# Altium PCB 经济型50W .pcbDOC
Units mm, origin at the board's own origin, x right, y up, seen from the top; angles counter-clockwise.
Board outline 67 x 32 mm, 2 copper layers (Top Layer, Bottom Layer); 38 components, 38 nets, 95 pads, 0 vias.
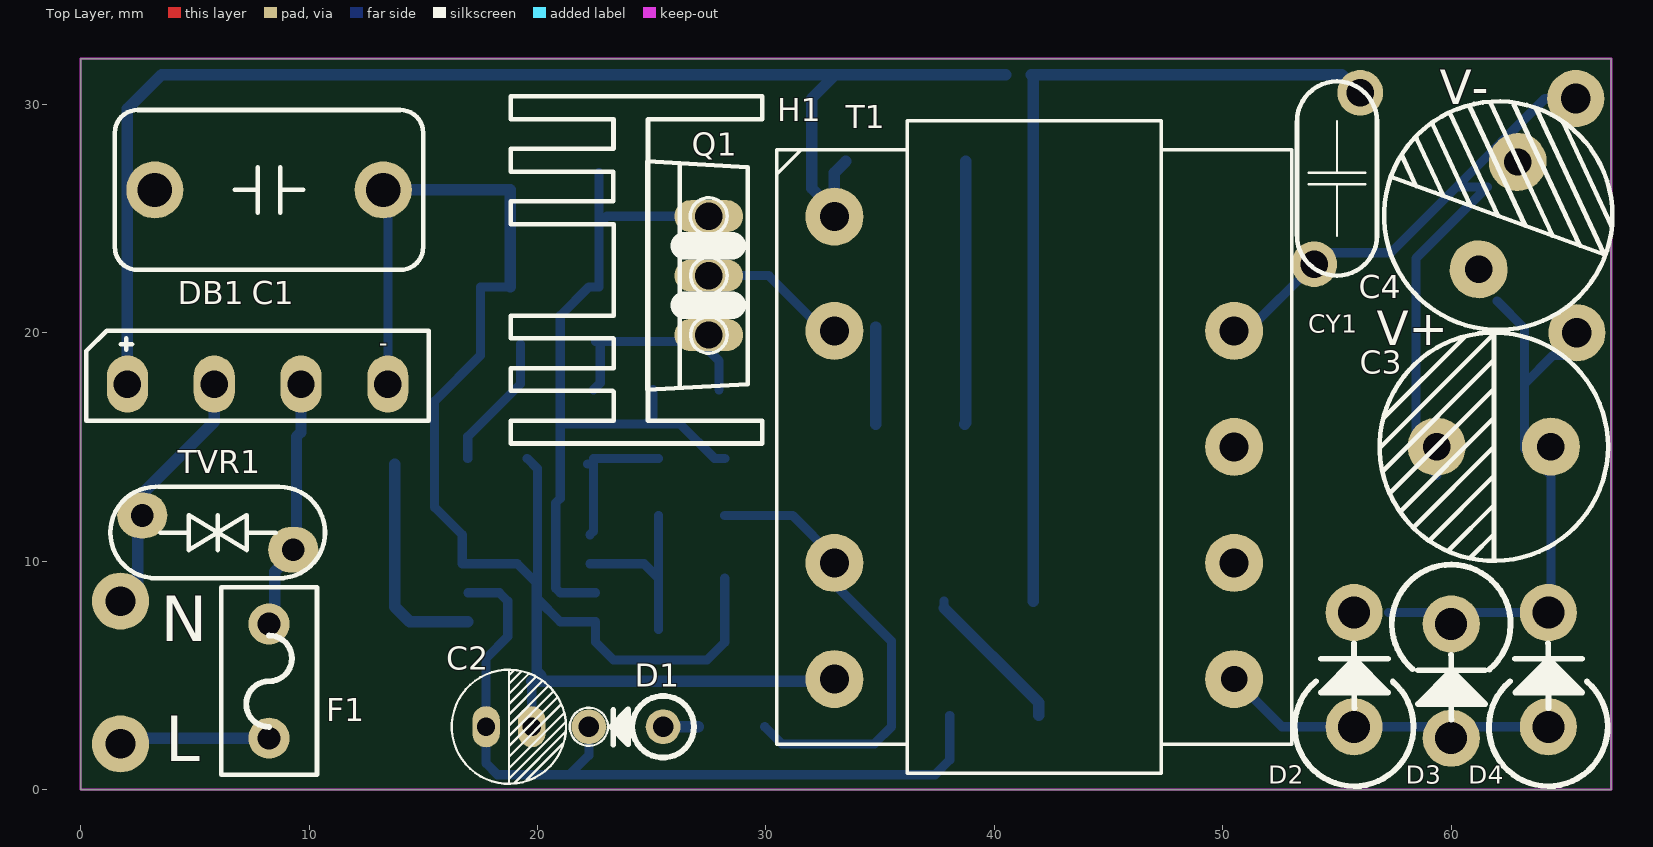
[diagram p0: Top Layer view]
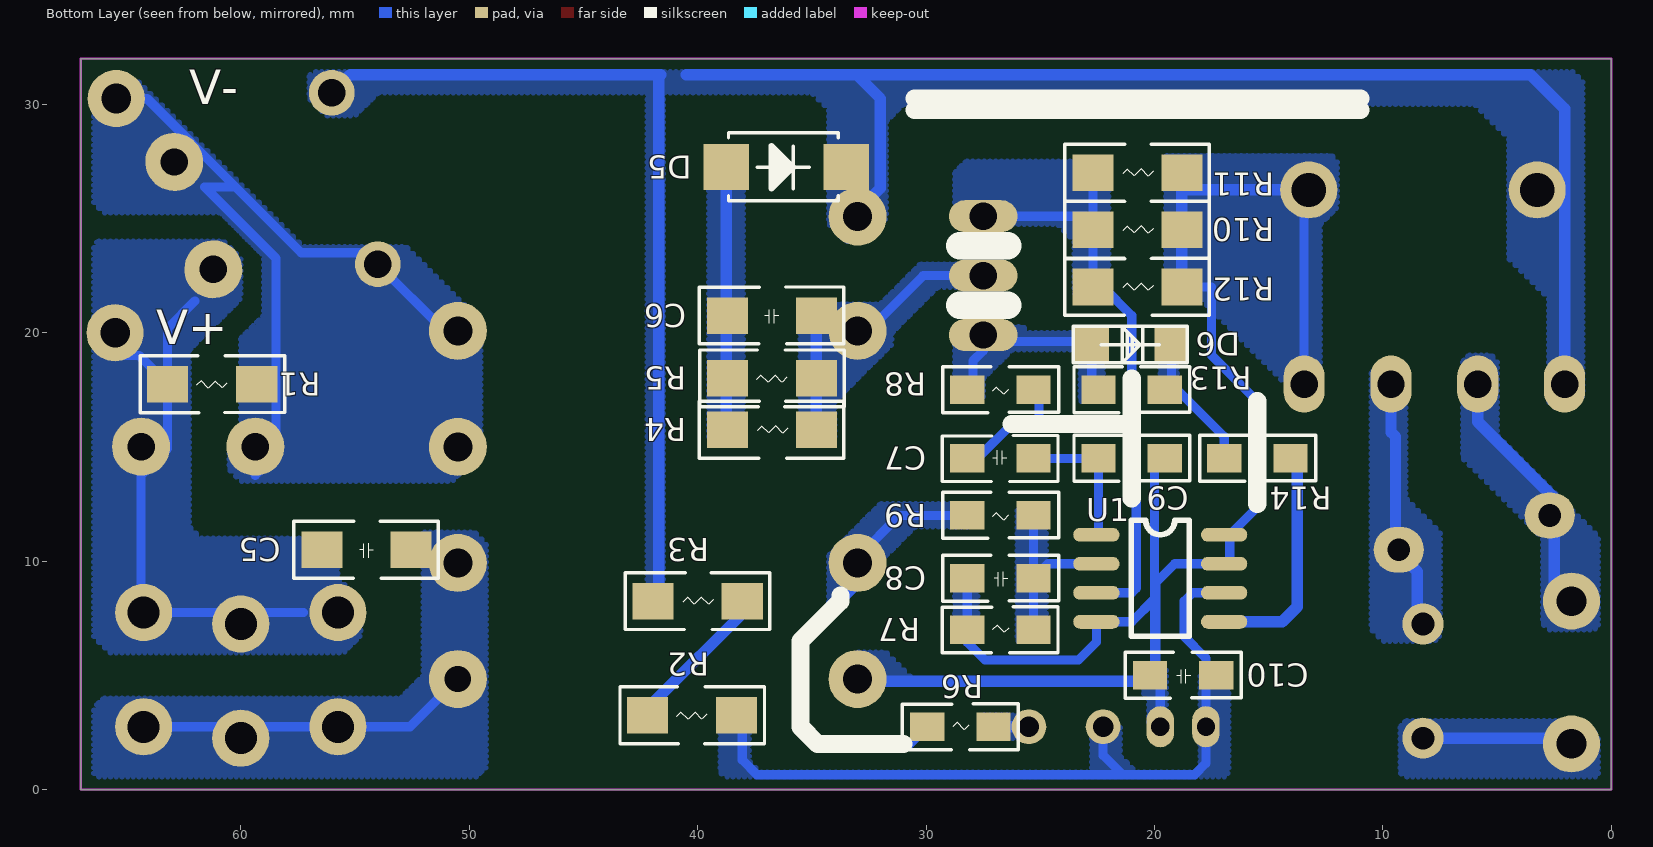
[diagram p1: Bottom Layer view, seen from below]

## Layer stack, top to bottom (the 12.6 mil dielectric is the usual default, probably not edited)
Top Solder: solder mask 0.0102, Solder Resist, Dk 3.5
Top Layer: signal copper 0.0356
Dielectric 1: dielectric 0.32, FR-4, Dk 4.8
Bottom Layer: signal copper 0.0356
Bottom Solder: solder mask 0.0102, Solder Resist, Dk 3.5

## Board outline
0,0 0,32 67,32 67,0

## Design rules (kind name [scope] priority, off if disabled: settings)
Clearance [All] p1: gap=0.4
FanoutControl Fanout_LCC [All] p1 off: bgadir=Out bgaviamode=Centered fanoutstyle=Auto fanoutdirection=Alternating viagrid=0.025 // Protel DXP Scope 1 Expression Was: IsLCC   Fanout_LCC (Default Rule)
FanoutControl Fanout_BGA [All] p2 off: bgadir=Out bgaviamode=Centered fanoutstyle=Auto fanoutdirection=Alternating viagrid=0.025 // Protel DXP Scope 1 Expression Was: IsBGA   Fanout_BGA (Default Rule)
FanoutControl Fanout_SOIC [All] p3 off: bgadir=Out bgaviamode=Centered fanoutstyle=Auto fanoutdirection=Alternating viagrid=0.025 // Protel DXP Scope 1 Expression Was: IsSOIC   Fanout_SOIC (Default Rule)
FanoutControl Fanout_Default [All] p4: bgadir=Out bgaviamode=Centered fanoutstyle=Auto fanoutdirection=Alternating viagrid=0.025 // Fanout_Default (Default Rule)
FanoutControl Fanout_Small [All] p5 off: bgadir=Out bgaviamode=Centered fanoutstyle=Auto fanoutdirection=Alternating viagrid=0.025 // Protel DXP Scope 1 Expression Was: (CompPinCount < 5)   Fanout_Small (Default Rule)
PlaneConnect [All] p1: planeconnectstyle=Direct reliefexpansion=0.508 reliefentries=4 reliefconductorwidth=0.254 reliefairgap=0.254
PolygonConnect [All] p1: connectstyle=Direct reliefconductorwidth=0.254 reliefentries=4 polygonreliefangle="90 Angle" airgapwidth=0.254
RoutingLayers [All] p1: top layer_v5=FALSE bottom layer_v5=TRUE
RoutingVias [All] p1: holewidth=0.711 width=1.27 viastyle="Through Hole" minholewidth=0.711 minwidth=1.27 maxholewidth=0.711 maxwidth=1.27
SilkToSolderMaskClearance [All] p1 off: minsilkscreentomaskgap=0.254 clearancetoexposedcopper=TRUE // Protel DXP Scope 1 Expression Was: IsPad
SolderMaskExpansion [All] p1: expansion=0.102
Width [All] p1: maxlimit=1 minlimit=0.2 preferedwidth=0.254
21 further rules are at their usual default settings.

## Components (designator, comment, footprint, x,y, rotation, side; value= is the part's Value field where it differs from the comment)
C1 "474 400V" "CBB电容 脚距10 长13mm 宽5mm" 8.25,26.25 r0 top
C2 "22uF/50V" "电解电容 脚距2mm 外径5mm" 18.75,2.75 r180 top
C3 "470uF 50V" "电解电容 脚距5mm 外径10mm" 62,15 r180 top
C4 "470uF 50V" "电解电容 脚距5mm 外径10mm" 62,25 r70 top
C5 "102/1KV" "电容 1206 背贴" 54.5,10.5 r180 bottom
C6 "103/1KV" "电容 1206 背贴" 36.75,20.75 r180 bottom
C7 "104 50V" "电容 0805 背贴"#1 26.75,14.5 r180 bottom
C8 "22pF 25V" "电容 0805 背贴"#1 26.75,9.25 r0 bottom
C9 "474 50V" "电容 0805 背贴"#1 21,14.5 r0 bottom
C10 "104/50V" "电容 0805 背贴"#2 18.75,5 r180 bottom
CY1 "102/250VAC" "Y2 电容 脚距7.5mm" 55,26.75 r90 top
D1 "1N4007" "二极管 DO41 脚距3.0mm" 25.5,2.75 r180 top
D2 "SF56" "二极管 DO201 脚距5.0MM" 55.75,5.25 r90 top
D3 "SF56" "二极管 DO201 脚距5.0mm_1" 60,4.75 r90 top
D4 "SF56" "二极管 DO201 脚距5.0MM" 64.25,5.25 r90 top
D5 "RS1M" "二极管 SMA" 36.25,27.25 r180 bottom
D6 "1N4148" "二极管 LL34" 21,19.5 r180 bottom
DB1 "KBP210" "桥堆 KBP" 7.75,17.75 r0 top
F1 "3.15A 250VAC" "保险丝 脚距5mm 长8mm 宽4mm" 8.25,4.75 r270 top
H1 "散热器" "散热片 长15mm 宽11mm 铝型材" 23.5,22.75 r0 top locked
Q1 "7N65" "功率开关管 TO220F-2" 27.5,22.5 r90 top
R1 "22K 5%" "电阻 1206 背贴"#1 61.25,17.75 r0 bottom
R2 "300K 5%" "电阻 1206 背贴"#2 40.25,3.25 r180 bottom
R3 "300K 5%" "电阻 1206 背贴"#2 40,8.25 r0 bottom
R4 "200K 5%" "电阻 1206 背贴"#1 36.75,15.75 r180 bottom
R5 "200K 5%" "电阻 1206 背贴"#1 36.75,18 r0 bottom
R6 "47R 5%" "电阻 0805 背贴"#1 28.5,2.75 r180 bottom
R7 "10K 1%" "电阻 0805 背贴"#2 26.75,7 r0 bottom
R8 "10K 5%" "电阻 0805 背贴"#2 26.75,17.5 r180 bottom
R9 "51K 1%" "电阻 0805 背贴"#2 26.75,12 r180 bottom
R10 "0.75R 1%" "电阻 1206 背贴"#2 20.75,27 r0 bottom
R11 "0.75R 1%" "电阻 1206 背贴"#2 20.75,24.5 r0 bottom
R12 "0.75R 1%" "电阻 1206 背贴"#2 20.75,22 r0 bottom
R13 "47R 5%" "电阻 0805 背贴"#1 21,17.5 r0 bottom
R14 "22R 5%" "电阻 0805 背贴"#2 15.5,14.5 r180 bottom
T1 "EFD25" 变压器ee28(5+5) 41.75,15 r0 top
TVR1 "7D511" "压敏电阻 直径7mm" 6,11.25 r90 top
U1 "LZC811C" "集成电路 SOP8 LZC811B" 19.75,9.25 r180 bottom

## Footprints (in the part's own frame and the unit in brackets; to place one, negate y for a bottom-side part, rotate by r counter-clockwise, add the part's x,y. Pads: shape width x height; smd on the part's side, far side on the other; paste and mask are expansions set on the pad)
"CBB电容 脚距10 长13mm 宽5mm" [mm] "插件"
  round 2.5 hole 1.5: 1(-5,0) 2(5,0)
  silkscreen extent -6.75,-3.5 6.75,3.5
"Y2 电容 脚距7.5mm" [mm] "插件"
  round 2 hole 1.2: 1(-3.75,1) 2(3.75,-1.016)
  silkscreen extent -4.25,-1.75 4.25,1.75
"二极管 DO41 脚距3.0mm" [mil] "插件"
  round 60 hole 35.43: 1(0,0) 2(127.95,0)
  silkscreen extent -53,-53 161,53
"二极管 DO201 脚距5.0MM" [mm] "插件"
  round 2.5 hole 1.4: 1(-2.5,0) 2(2.5,0)
  silkscreen extent -5.1,-2.6 1.15,2.6
"二极管 DO201 脚距5.0mm_1" [mm] "插件"
  round 2.5 hole 1.4: 1(-2.5,0) 2(2.5,0)
  silkscreen extent -1.68,-2.6 5.1,2.6
"二极管 LL34" [mm] "贴片"
  rect 1.5x1.5 smd: 1(-1.75,0) 2(1.75,0)
  silkscreen extent -2.56,-0.82 2.44,0.78
"二极管 SMA" [mm] "贴片"
  rect 2x2 smd: 1(-2.5,0) 2(2.75,0)
  silkscreen extent -2.4,-1.48 2.4,1.49
"保险丝 脚距5mm 长8mm 宽4mm" [mm] "贴片"
  round 1.8 hole 1: 1(-2.5,0) 2(2.5,0)
  silkscreen extent -4.1,-2.1 4.1,2.1
"功率开关管 TO220F-2" [mm] "插件"
  oval 1.4x3 hole 1.2: D(0,0) G(-2.6,0) S(2.6,0)
  silkscreen extent -5,-1.7 5,2.7
"压敏电阻 直径7mm" [mm] "插件"
  oval 2x2.2 hole 1: 1(-0.75,-3.31) 2(0.75,3.3)
  silkscreen extent -2,-4.7 2,4.7
变压器ee28(5+5) [mm] "插件"
  round 0 all layers, no hole: 0(8.75,5.08) ""(-8.731,10.16)
  round 2.54 hole 1.27: 1(-8.75,10.08) 2(-8.75,5.08) 4(-8.75,-5.08) 5(-8.75,-10.16) 7(8.75,-5.08) 8(8.75,0) 9(8.75,5.08)
  round 2.54 hole 1.143: 6(8.75,-10.16)
  silkscreen extent -11.27,-14.29 11.27,14.29
"散热片 长15mm 宽11mm 铝型材" [mm] "配件"
  silkscreen extent -4.66,-7.6 6.34,7.6
"桥堆 KBP" [mm] "插件"
  oval 1.8x2.5 hole 1.2: 1(-5.7,0) 2(-1.9,0) 3(1.9,0) 4(5.7,0)
  silkscreen extent -7.5,-1.6 7.5,2.34
"电容 0805 背贴"#1 [mm] "贴片"
  rect 1.5x1.25 smd: 1(1.45,0) 2(-1.45,0)
  silkscreen extent -2.55,-1.01 2.52,1
"电容 0805 背贴"#2 [mm] "贴片"
  rect 1.5x1.25 smd: 1(-1.45,0) 2(1.45,0)
  silkscreen extent -2.52,-1 2.55,1.01
"电容 1206 背贴" [mm] "贴片"
  rect 1.8x1.6 smd: 1(-1.95,0) 2(1.95,0)
  silkscreen extent -3.17,-1.24 3.15,1.25
"电解电容 脚距2mm 外径5mm" [mm] "插件"
  oval 1.2x1.8 hole 0.8: 1(1,0) 2(-1,0)
  silkscreen extent -2.5,-2.5 2.5,2.5
"电解电容 脚距5mm 外径10mm" [mm] "插件"
  round 2.54 hole 1.2: 1(-2.364,-0.01) 2(2.636,-0.01)
  silkscreen extent -4.86,-5.01 5.13,4.99
"电阻 0805 背贴"#1 [mm] "贴片"
  rect 1.5x1.25 smd: 1(1.45,0) 2(-1.45,0)
  silkscreen extent -2.55,-1.01 2.52,1
"电阻 0805 背贴"#2 [mm] "贴片"
  rect 1.5x1.25 smd: 1(-1.45,0) 2(1.45,0)
  silkscreen extent -2.52,-1 2.55,1.01
"电阻 1206 背贴"#1 [mm] "贴片"
  rect 1.8x1.6 smd: 1(-1.95,0) 2(1.95,0)
  silkscreen extent -3.17,-1.24 3.15,1.25
"电阻 1206 背贴"#2 [mm] "贴片"
  rect 1.8x1.6 smd: 1(1.95,0) 2(-1.95,0)
  silkscreen extent -3.15,-1.25 3.17,1.24
"集成电路 SOP8 LZC811B" [mil] "贴片"
  oval 80x24 smd: CMP(-110,75) CS(-110,-25) DRV(110,-75) FB(-110,25) GND(-110,-75) NC(110,25) NC(110,75) VDD(110,-25)
  silkscreen extent -50,-100 50,100

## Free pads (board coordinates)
  round 2.5 hole 1.3: 0(1.75,8.25) 1(1.75,2) 1(65.453,30.25) 1(65.5,20)

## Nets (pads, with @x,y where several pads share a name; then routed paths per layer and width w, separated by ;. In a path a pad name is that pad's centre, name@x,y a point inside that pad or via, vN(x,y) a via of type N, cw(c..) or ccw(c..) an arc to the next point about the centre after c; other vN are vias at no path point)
CMP: C7.1 C9.1 U1.CMP | length 6.3
  Bottom Layer w0.4: C9.1@22.2,14.25 22.45,14.25 22.45,11.311 U1.CMP@22.294,11.155 ; C9.1 C7.1
CS: C7.2 Q1.S R8.2 R10.1 R11.1 R12.1 U1.CS | length 35.5
  Bottom Layer w0.4: U1.CS 21,8.615 20.8,8.815 20.8,12.55 21,12.75 21,15.665 21,16 ; R10.1 R11.1@22.7,24.75 ; R8.2@25.05,17.5 25.05,16.3 24.75,16 ; Q1.S 23.05,25.1 R11.1@22.7,24.75 ; C7.2 27.75,14.5 26.25,16 24.75,16 ; 21,16 24.75,16 ; 21,16 21,20.75 22.25,22 R12.1 R11.1 R11.1@22.7,24.75
DRV: R14.2 U1.DRV | length 9.7
  Bottom Layer w0.5: R14.2@13.75,14.25 13.75,8 14.405,7.345 U1.DRV
E: 
E2: 
E3: 
FB: C8.2 R7.1 R9.2 U1.FB | length 8.3
  Bottom Layer w0.4: U1.FB@22.294,9.885 24.665,9.885 C8.2 ; R7.1 R9.2
G: D6.2 R13.2 R14.1 | length 6
  Bottom Layer w0.4: R14.1 16.95,15.45 19.25,17.75 D6.2
G1: 
g2: D6.1 Q1.G R8.1 R13.1 | length 9.2
  Bottom Layer w0.4: R13.1 22.75,17.8 D6.1 ; D6.1@22.547,19.61 27.297,19.61 27.5,19.21 27.95,18.76 R8.1@27.95,17.5
GND: C3.2 C4.2 CY1.1 pad.1@65.453,30.25 R1.1 T1.8 T1.9 | length 35.2
  Bottom Layer w0.4: T1.9 51.08,20.08 CY1.1 54.5,23.5 57.354,23.5 60.24,26.386 ; C3.2@59.364,13.76 58.453,14.672 58.453,23.25 61.588,26.386 60.24,26.386 ; pad.1@65.5,29.5 64.75,30.25 64.104,30.25 60.24,26.386
GND1: 
GND2: 
GNDE: C1.2 C2.2 C8.1 C9.2 C10.1 DB1.4 R7.2 R10.2 R11.2 R12.2 T1.5 U1.GND U1.NC | length 79.5
  Bottom Layer w0.4: C1.2@12.75,26.25 13.45,25.55 DB1.4 DB1.4@13.45,17.465 ; R12.2 17.5,22 17.5,19 15.5,17 15.5,12.361 16.706,11.155 16.706,9.885 19.115,9.885 19.949,9.051 19.949,5 19.75,4.801 19.75,4.75 C2.2 ; C9.2 20,14.05 20,8.342 ; C10.1 20,5.2 20,8.342 ; 20.5,7.842 20,8.342 ; C8.1 28.2,6.45 27.425,5.675 23.325,5.675 22.544,6.456 U1.GND 20.997,7.345 20,8.342
  Bottom Layer w0.5: C1.2@12.75,26.25 18.8,26.25 R11.2 R12.2 ; C10.1@19.75,4.75 T1.5@31.75,4.75
HV1: C6.1 D5.1 R4.1 R5.2 | length 11.5
  Bottom Layer w0.5: R4.1@38.7,16 38.75,16.05 D5.1@38.75,27.5
L: F1.2 pad.1@1.75,2 | length 6
  Bottom Layer w0.5: pad.1@1.75,2.25 F1.2@7.75,2.25
L0: DB1.3 F1.1 TVR1.1 | length 11.3
  Bottom Layer w0.5: F1.1@7.75,7.25 8.5,8 8.5,9.547 9.453,10.5 9.453,15.453 9.65,15.65 DB1.3
L1: 
L2: 
LED+: 
LED-: 
LN: 
N: 
N0: DB1.2 pad.0 TVR1.2 | length 11.9
  Bottom Layer w0.5: pad.0 2.5,9 2.5,12.25 2,12.25 5.85,16.1 DB1.2
N1: 
N3: 
ST: R2.2 R3.2 | length 6.7
  Bottom Layer w0.4: R3.2@37.8,7.95 R3.2@37.8,8.25
  Bottom Layer w0.5: R3.2@37.8,7.95 41.95,3.8 R2.2@41.95,3.25
TA: R6.2 R9.1 T1.4 | length 20.2
  Bottom Layer w0.4: R9.1 31.17,12 33,10.17 33,9 35.5,6.5 35.5,2.75 34.75,2 30.7,2 R6.2
TA1: D1.1 R6.1 | length 1.8
  Bottom Layer w0.5: D1.1@25.25,2.75 R6.1
TS: C5.2 D2.1 D3.1 D4.1 T1.6 T1.7 | length 14.4
  Bottom Layer w0.4: T1.6 52.59,2.75 57.25,2.75 D4.1@64,2.75
TS1: 
VBUS: C1.1 CY1.2 D5.2 DB1.1 R3.1 T1.1 | length 98.1
  Bottom Layer w0.5: DB1.1 2.05,29.8 3.55,31.3 33.05,31.3 ; D5.2@33.5,27.5 33,27 33,25.33 32,26.33 32,30.25 33.05,31.3 ; 40.5,31.3 33.05,31.3 ; R3.1@41.7,8.25 41.7,31.215 41.615,31.3 55.216,31.3 CY1.2
VBUS1: 
VBUS2: 
VBUS3: 
VDD: C2.1 C10.2 D1.2 R2.1 U1.VDD | length 34.8
  Bottom Layer w0.4: U1.VDD 18.335,8.615 18.7,8.25 18.7,6.7 17.75,5.75 C2.1 17.75,1.15 18.25,0.65 37.4,0.65 38.05,1.3 R2.1@38.05,3.25 ; 21.4,0.65 22.25,1.5 22.25,2.25 D1.2@22.75,2.75
VDS: C6.2 Q1.D R4.2 R5.1 T1.2 | length 10.6
  Bottom Layer w0.4: Q1.D 30.125,22.5 32.295,20.33 T1.2@33,20.33
  Bottom Layer w0.5: R4.2@34.8,16 34.8,17.375 C6.2@34.8,20.25
VOUT: C3.1 C4.1 C5.1 D2.2 D3.2 D4.2 pad.1@65.5,20 R1.2 | length 24.3
  Bottom Layer w0.4: 57.25,7.75 64,7.75 64.364,8.114 64.364,13.76 63.2,14.925 R1.2 ; 62.01,21.386 63.2,20.196 R1.2 ; pad.1@65.5,19 64.45,19 R1.2
pads on no net: T1. T1.0

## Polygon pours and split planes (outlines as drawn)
no net on Keep-Out Layer (hatched 90Degree grid 0.2 track 0.2): 25.335,8.035
no net on Keep-Out Layer (hatched 90Degree grid 0.2 track 0.2): 99.31,2.685
no net on Keep-Out Layer (hatched 90Degree grid 0.2 track 0.203): 5.885,-7.515
L0 on Bottom Layer "Bottom Layer-No Net" (hatched 90Degree grid 0.25 track 0.25, remove dead copper, pour order 35): 10.25,18.5 10.5,18.25 10.5,7 10,6.5 7.75,6.5 7.5,6.75 7.5,11.25 9,12.75 9,18.25 9.25,18.5
N0 on Bottom Layer "Bottom Layer-No Net" (hatched 90Degree grid 0.25 track 0.25, remove dead copper, pour order 33): 0.5,11 5,15.5 5,18.75 5.25,19 6.25,19 6.5,18.75 6.5,14.5 3,11 3,7.25 2.75,7 0.75,7 0.5,7.25
GNDE on Bottom Layer "Bottom Layer-No Net" (hatched 90Degree grid 0.25 track 0.25, remove dead copper, pour order 28): 33,6 31.75,6 30.5,4.75 32,4.75 33,3.75 33.25,3.75 33.25,4.25 33.5,4.5 33.25,4.75 33.25,5.75
L on Bottom Layer "Bottom Layer-No Net" (hatched 90Degree grid 0.25 track 0.25, remove dead copper, pour order 37): 1.5,3 6.25,3 9,3 9.25,2.75 9.25,2.25 9.25,0.75 8.75,0.25 3.5,0.25 0.75,0.25 0.5,0.5 0.5,1.5 0.5,2.25 1.25,3
VBUS on Bottom Layer "Bottom Layer-No Net" (hatched 90Degree grid 0.25 track 0.25, remove dead copper, pour order 39): 1.25,17.25 1.25,31 2,31.75 56.5,31.75 57,31.25 57,30.25 56.25,29.5 55,29.5 54,30.5 35,30.5 34.25,29.75 34.25,24.75 33.5,24 32.75,24 31.75,25 31.75,29.25 31,30 6,30 4.5,28.5 4.5,23.25 2.75,21.5 2.75,17 2.5,16.75 1.75,16.75 1.5,17
VDS on Bottom Layer "Bottom Layer-No Net" (hatched 90Degree grid 0.25 track 0.25, remove dead copper, pour order 41): 26.75,22 29.5,22 31.5,20 31.5,19.5 34,17 34,15.25 35.5,15.25 35.5,21.25 32,21.25 30.25,23 26.75,23
g2 on Bottom Layer "Bottom Layer-No Net" (hatched 90Degree grid 0.25 track 0.25, remove dead copper, pour order 43): 28.75,17 27.5,17 27.5,18 26.25,19.25 23.5,19.25 23.25,19 23.25,17 22.25,17 22.25,20 25.5,20 25.75,20.25 28.75,20.25
HV1 on Bottom Layer "Bottom Layer-No Net" (hatched 90Degree grid 0.25 track 0.25, remove dead copper, pour order 45): 38,27.75 38,15.25 39.5,15.25 39.5,18.25 39.5,24 39.5,27.75
VBUS on Bottom Layer "Bottom Layer-No Net" (hatched 90Degree grid 0.25 track 0.25, remove dead copper, pour order 47): 42.203,8 42.203,30.96 41.5,30.96 41.5,8
GNDE on Bottom Layer "Bottom Layer-No Net" (hatched 90Degree grid 0.25 track 0.25, remove dead copper, pour order 49): 12.75,17.5 12.75,24.75 12,25.5 12,27.5 12.25,27.75 19.5,27.75 19.5,21.5 18,21.5 14,17.5 13.485,17.5 13.45,17.465
TA on Bottom Layer "Bottom Layer-No Net" (hatched 90Degree grid 0.25 track 0.25, remove dead copper, pour order 51): 28,12.5 31,12.5 32,12.5 33.75,10.75 34,10.5 34,9.25 33.75,9 32.75,9 32.75,9.25 31.75,10.25 30.5,11.5 28,11.5
GNDE on Bottom Layer "Bottom Layer-No Net" (hatched 90Degree grid 0.25 track 0.25, remove dead copper, pour order 53): 28.75,9.75 28.75,6.5 27.75,6.5 27.75,9.75
FB on Bottom Layer "Bottom Layer-No Net" (hatched 90Degree grid 0.25 track 0.25, remove dead copper, pour order 55): 25.75,12.25 26,12.25 26,6.5 24.75,6.5 24.75,12.25
CS on Bottom Layer "Bottom Layer-No Net" (hatched 90Degree grid 0.25 track 0.25, remove dead copper, pour order 57): 22,27.5 22,21.5 23.25,21.5 23.5,21.75 23.5,24 24.25,24.75 28.75,24.75 28.75,27 28.25,27.5
VDD on Bottom Layer "Bottom Layer-No Net" (hatched 90Degree grid 0.25 track 0.25, remove dead copper, pour order 59): 16.75,5 16.75,0.75 17.25,0.25 19.75,0.25 38.5,0.25 39,0.75 39,2.5 39,3 37.75,3 37.75,1.25 37.25,0.75 36.5,0.75 18.25,0.75 18,1 18,2.25 18,5
VDD on Bottom Layer "Bottom Layer-No Net" (hatched 90Degree grid 0.25 track 0.25, remove dead copper, pour order 61): 21.75,3 21.5,2.75 21.5,1.75 21.5,1.46 20.703,0.663 20.79,0.575 22.453,0.575 22.75,0.872 22.75,2.75 22.5,3
TA1 on Bottom Layer "Bottom Layer-No Net" (hatched 90Degree grid 0.25 track 0.25, remove dead copper, pour order 63): 25.25,3.25 27.5,3.25 27.5,2.25 25,2.25
TA on Bottom Layer "Bottom Layer-No Net" (hatched 90Degree grid 0.25 track 0.25, remove dead copper, pour order 65): 33.04,11.46 34.25,10.25 34.25,8.25 34.25,8 34,8 31.703,10.297
GNDE on Bottom Layer "Bottom Layer-No Net" (hatched 90Degree grid 0.25 track 0.25, remove dead copper, pour order 9): 19.5,2.75 19.5,5.25 20.5,5.25 20.5,4.25 20.25,4 20.25,3.25 20.25,2.75
TS on Bottom Layer "Bottom Layer-No Net" (hatched 90Degree grid 0.25 track 0.25, remove dead copper, pour order 70): 49.25,1 50,0.25 66.5,0.25 66.75,0.5 66.75,3.25 66,4 53,4 52,5 52,11.25 49.75,11.25 49.25,10.75
GND on Bottom Layer "Bottom Layer-No Net" (hatched 90Degree grid 0.25 track 0.25, remove dead copper, pour order 68): 49.5,20.5 52.75,23.75 57.25,23.75 64.5,31 66.25,31 66.75,30.5 66.75,26 66,25.25 60.875,25.25 59,23.375 59,20.75 60,19.75 60,15.25 60.5,14.75 60.5,14 60,13.5 50.75,13.5 49.5,14.75
VOUT on Bottom Layer "Bottom Layer-No Net" (hatched 90Degree grid 0.25 track 0.25, remove dead copper, pour order 72): 55.25,6.25 55.5,6 65.75,6 66.75,7 66.75,23.5 66.25,24 60.75,24 60,23.25 60,21.5 62.25,19.25 62.25,11.5 61.75,11 56,11 55.75,10.75 55.75,9.25 54.75,8.25 54.75,6.75
G on Bottom Layer "Bottom Layer-No Net" (hatched 90Degree grid 0.25 track 0.25, remove dead copper, pour order 74): 19.5,19.5 19.75,19.25 19.75,17.75 19,17.75 19,19.5

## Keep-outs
Keep-Out Layer:
  the board outline again, w0.1

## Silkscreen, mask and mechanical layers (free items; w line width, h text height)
Top Overlay:
  text "V-" at 59.5,30 h1.5
  text "V+" at 56.75,19.46 h1.5
  text "N" at 3.5,6.5 h2
  text "L" at 3.703,1.25 h2
Bottom Overlay:
  lines w0.8: 11,29.75 30.5,29.75 ; 11,30.25 30.5,30.25 ; 15.5,12.5 15.5,17 ; 21,12.75 21,18 ; 21,16 26.25,16 ; 31,2 34.75,2 35.5,2.75 ; 33.75,8.5 33.75,8.25 35.5,6.5 35.5,5 35.5,2.75 ; 35.5,2.75 35.5,2.75
  text "V-" at 62.25,30 h1.5
  text "V+" at 63.703,19.5 h1.5

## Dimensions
0,0 to 0,32 on Keep-Out Layer
0,0 to 67,0 on Keep-Out Layer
